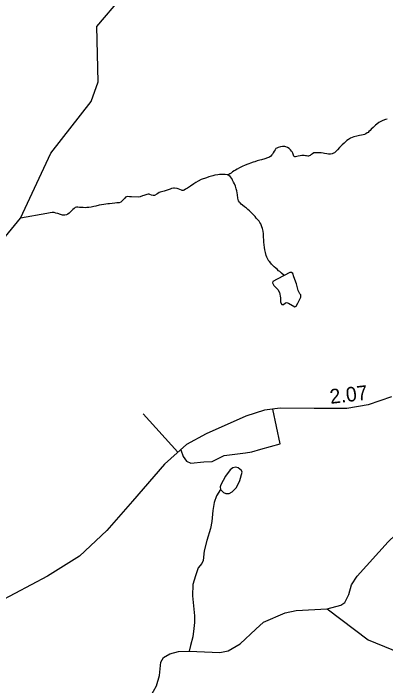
# Model space of a CAD drawing. Extents: x 2056842 to 2160602, y 826753 to 1016856.
# Drawn here: x 2117511 to 2120707, y 858312 to 864081 of the extents above; entities that cross this region are included whole.
import ezdxf

# ---------------------------------------------------------------- set-up
doc = ezdxf.new("R2010")
doc.units = 0
for name, color, linetype in [('Exist Hydrographic Creek Single Shore', 7, 'Continuous'), ('Exist Hydrographic Misc Water Feature', 7, 'Continuous'), ('Exist Road Non-System Type 51', 7, 'Continuous'), ('Exist Road Secondary Mileage Hundredths English Label', 7, 'Continuous'), ('Exist Road Secondary Type 51 Attributed', 7, 'Continuous')]:
    doc.layers.add(name, color=color, linetype=linetype)

msp = doc.modelspace()

# ---------------------------------------------------------------- linework, layer by layer
at = {"layer": 'Exist Hydrographic Creek Single Shore'}
for points in [[(2116978.9, 861602.5), (2117571.4, 862322.8), (2117831.9, 862880.9), (2118179.9, 863326.5), (2118237.9, 863492.7), (2118226.8, 863968.7), (2118442.7, 864224.9)], [(2120721.8, 863174.4), (2120706.1, 863169.9), (2120684.1, 863162.3), (2120666.1, 863153.7), (2120650.5, 863143.9), (2120632.2, 863129.6), (2120622, 863121.8), (2120612.8, 863113.9), (2120600.3, 863103.2), (2120584.5, 863087.4), (2120574.6, 863076.6), (2120565, 863067.2), (2120556.6, 863059.9), (2120549, 863055.4), (2120538.9, 863048.8), (2120525.2, 863042.4), (2120515, 863040.2), (2120501.2, 863036.2), (2120484.8, 863032.6), (2120461.2, 863028.1), (2120435.2, 863022.3), (2120419.2, 863015.8), (2120405.5, 863009.8), (2120389.7, 862999.6), (2120375.7, 862989.2), (2120351.9, 862968.8), (2120333.9, 862952.9), (2120312.4, 862930.5), (2120294.5, 862910.1), (2120286.1, 862900.8), (2120268.5, 862886), (2120259.5, 862880.5), (2120249, 862876.8), (2120235.5, 862874.4), (2120218.4, 862874.1), (2120202.7, 862876.2), (2120182.8, 862879.6), (2120170.5, 862881.8), (2120154.5, 862883.9)], [(2120154.5, 862883.9), (2120134.8, 862884.8), (2120120.4, 862885.4), (2120106.7, 862884.6), (2120092.3, 862883.2), (2120080.2, 862876.8), (2120072.4, 862870.8), (2120066.7, 862866.8), (2120061, 862862.8), (2120052.6, 862858.7), (2120046.6, 862856.4), (2120038.6, 862856.4), (2120028.8, 862858.2), (2120018.9, 862860.2), (2120008.7, 862862.1), (2120000.5, 862862.1), (2119989, 862861.4), (2119972.8, 862859.4), (2119957, 862855.8), (2119944.9, 862851.9), (2119934.7, 862849.7), (2119928.7, 862849.8), (2119923.8, 862853), (2119920.7, 862857.2), (2119917, 862865.4), (2119910.7, 862881.4), (2119904.5, 862892.9), (2119900.4, 862899.6), (2119892.2, 862909), (2119878.1, 862922.8), (2119864.9, 862931.3), (2119850.2, 862936.9), (2119842, 862938.5), (2119822.1, 862939), (2119804.2, 862936.1), (2119783.9, 862929.8), (2119774.5, 862926), (2119766.3, 862920.4), (2119758.3, 862910.6), (2119749.3, 862897.7), (2119742.3, 862884.2), (2119736.4, 862873.3), (2119730, 862866.1), (2119722.2, 862857.2), (2119709.7, 862848.6), (2119694.1, 862841.6), (2119669.3, 862833.1), (2119640.8, 862825.3), (2119627.3, 862820.8), (2119605.5, 862814.9), (2119585.2, 862808.5), (2119571.1, 862804.6), (2119547.5, 862796), (2119531.7, 862790.7), (2119515.3, 862783.8), (2119495.4, 862775.9), (2119481.5, 862769.5), (2119469.4, 862763.2), (2119452.8, 862754.8), (2119433.7, 862745.1), (2119419.6, 862737.1), (2119408.1, 862729.5), (2119393.9, 862720.7), (2119380, 862711), (2119370.4, 862703.9), (2119362.1, 862698.3), (2119353.7, 862695.9)], [(2119353.7, 862695.9), (2119348.2, 862695.9), (2119330.8, 862699), (2119310.3, 862700), (2119292.2, 862699.5), (2119280.5, 862698.5), (2119266.6, 862696.2), (2119242.2, 862691.7), (2119224.8, 862687), (2119190.7, 862678.8), (2119168.6, 862671.2), (2119152.6, 862664.7), (2119140.5, 862660.9), (2119122.4, 862654.7), (2119097, 862642.3), (2119076.7, 862630.3), (2119059.5, 862618.3), (2119031.4, 862597.5), (2119023.2, 862592.2), (2119005.4, 862581.9), (2118989.6, 862571.4), (2118977.9, 862565), (2118968.4, 862561.9), (2118960, 862562), (2118953.9, 862563), (2118941.6, 862569.2), (2118927.4, 862575.1), (2118917.8, 862578.6), (2118895.5, 862582.3), (2118885.2, 862582.7), (2118870, 862578), (2118857.7, 862572.6), (2118841.3, 862566.2), (2118822.9, 862560.1), (2118806, 862555.7), (2118783.7, 862549.3), (2118771.8, 862547.1), (2118764, 862543.4), (2118751.9, 862535.1), (2118742.1, 862528.9), (2118722.2, 862518.9), (2118710.3, 862519.1), (2118695.9, 862522.5), (2118683.8, 862526.8), (2118676.5, 862530.4), (2118667.8, 862530.4), (2118657.8, 862528.3), (2118631.8, 862518), (2118620.1, 862514.1), (2118600, 862508.2), (2118581.9, 862503.6), (2118525.9, 862507.3), (2118507.7, 862507.6), (2118492.1, 862508.7), (2118482.3, 862507.4), (2118474.3, 862503.3), (2118464, 862492.7), (2118454.2, 862482.4), (2118448.2, 862474.4), (2118442.7, 862468.7), (2118433.5, 862461.7), (2118420.5, 862456.6), (2118400.7, 862454), (2118382.8, 862451.8), (2118358.8, 862449.8), (2118336.7, 862447.8), (2118320.7, 862445.8), (2118304.7, 862443.8), (2118287.3, 862441.6), (2118269, 862439.4), (2118248.7, 862435.2), (2118219, 862426.7), (2118200.9, 862423), (2118178.8, 862418.2), (2118158.9, 862416.4), (2118141.3, 862414.2), (2118127.1, 862413.5), (2118108.9, 862414.2), (2118089, 862415.1), (2118077.5, 862416.6), (2118063.1, 862417.5), (2118052.1, 862417.5), (2118041.8, 862414.6), (2118033.4, 862407.3), (2118022.7, 862397.6), (2118011.3, 862386.8), (2118001.6, 862376.9), (2117989.5, 862366.5), (2117977.4, 862357), (2117968, 862351.6), (2117953.9, 862348.4), (2117933.3, 862350.3), (2117914.3, 862355.7), (2117893.4, 862362.8), (2117875.5, 862368), (2117860.3, 862371.5), (2117843.3, 862371.2), (2117827.7, 862369.1), (2117797.4, 862363.1), (2117571.4, 862322.8)]]:
    msp.add_lwpolyline(points, dxfattribs=at)
at = {"layer": 'Exist Hydrographic Misc Water Feature'}
for points in [[(2119835.3, 861830.9), (2119812.4, 861853.1), (2119798.3, 861865), (2119788, 861872.6), (2119776.6, 861884.9), (2119764.3, 861895.3), (2119751.3, 861907), (2119739.6, 861917.7), (2119728.2, 861928.7), (2119712, 861948.6), (2119706, 861956), (2119696, 861972.2), (2119687.6, 861988.4), (2119681.4, 862004.4), (2119675.1, 862028.1), (2119671, 862052.2), (2119667.1, 862071.9), (2119664, 862094.6), (2119662.3, 862118), (2119661.1, 862140.2), (2119660.3, 862158.2), (2119658, 862173.9), (2119657.8, 862190.2), (2119656, 862211.5), (2119649.4, 862234.1), (2119645.1, 862249.2), (2119639, 862266.1), (2119635.3, 862276), (2119628.9, 862286.7), (2119620.9, 862297.6), (2119607, 862313.5), (2119596.7, 862325.2), (2119586.9, 862337.6), (2119574.8, 862349.2), (2119562.5, 862362.8), (2119550.6, 862375.2), (2119538.5, 862387.1), (2119524.3, 862398.6), (2119512, 862409.1), (2119496, 862420.8), (2119479.6, 862434.2), (2119466.5, 862445.2), (2119457.5, 862454.2), (2119452, 862461.6), (2119445.6, 862471.8), (2119439.2, 862495.5), (2119435.1, 862523.7), (2119433.1, 862540.3), (2119430, 862557.3), (2119424.7, 862575.7), (2119418.5, 862597.6), (2119410.3, 862617.6), (2119401.9, 862633.4), (2119393.9, 862649.3), (2119386.1, 862663.4), (2119372.8, 862680.1), (2119353.7, 862695.9)], [(2119835.3, 861830.9), (2119777.5, 861800.7), (2119738.6, 861779.3), (2119737.3, 861768), (2119747.4, 861746.7), (2119781.3, 861711.5), (2119797.6, 861685.1), (2119803.9, 861639.9), (2119806.4, 861602.2), (2119816.4, 861583.3), (2119830.2, 861583.3), (2119846.6, 861598.4), (2119856.6, 861600.9), (2119874.2, 861593.4), (2119929.4, 861563.2), (2119939.5, 861569.5), (2119954.6, 861593.4), (2119978.4, 861644.9), (2119979.7, 861666.3), (2119972.1, 861675.1), (2119957.1, 861702.7), (2119942, 861759.2), (2119920.7, 861820.8), (2119911.9, 861848.4), (2119899.3, 861857.2), (2119885.5, 861857.2), (2119835.3, 861830.9)], [(2120205.7, 858970), (2120322.9, 859000.6), (2120356.4, 859024), (2120392.8, 859093.1), (2120413.7, 859175.9), (2120463.1, 859250.2), (2120728.9, 859546.7), (2120986.7, 859793), (2121019.8, 859839.3), (2121060.9, 859946.7), (2121084.7, 860097), (2121152.5, 860255.3), (2121202.7, 860369.6), (2121265.7, 860615.1), (2121373.8, 860757.3), (2121522.8, 860872.3), (2121913.4, 861039.3), (2122082.9, 861099.6), (2122200.9, 861098.4), (2122526.2, 861098.4), (2122650.5, 861131), (2122864, 861225)], [(2119290.3, 859995.2), (2119314.2, 859968.9), (2119334.2, 859960.1), (2119363.1, 859960.1), (2119390.7, 859973.9), (2119427.2, 860011.6), (2119456, 860070.6), (2119476.1, 860144.7), (2119471.1, 860158.6), (2119442.2, 860181.2), (2119420.9, 860186.2), (2119395.8, 860181.2), (2119373.2, 860163.6), (2119331.7, 860108.3), (2119291.6, 860035.4), (2119286.5, 860016.6), (2119290.3, 859995.2)], [(2119290.3, 859995.2), (2119255.1, 859940), (2119236.3, 859883.4), (2119223.7, 859815.6), (2119215, 859720.1), (2119203.7, 859661), (2119172.3, 859558), (2119149.7, 859468.8), (2119140.9, 859384.6), (2119129.6, 859359.5), (2119096.9, 859321.8), (2119074.3, 859254), (2119051.7, 859178.6), (2119050.5, 859080.6), (2119059.3, 858966.2), (2119066.8, 858909.7), (2119066.8, 858854.4), (2119061.8, 858800.4), (2119051.7, 858728.8), (2119032.9, 858654.6), (2119020.3, 858606.9)], [(2117222.2, 857915.9), (2117523.2, 858055), (2117847.5, 858181), (2117970.6, 858189.8), (2118555.7, 858109.4), (2118585.9, 858121.9), (2118662.5, 858172.2), (2118739.1, 858309.1), (2118766.7, 858397.1), (2118778, 858513.9), (2118799.3, 858551.6), (2118855.8, 858585.5), (2118929.9, 858603.1), (2119020.3, 858606.9), (2119282.8, 858594.3), (2119355.6, 858610.7), (2119458.6, 858671), (2119594.2, 858796.6), (2119657.9, 858856.9), (2119845.3, 858937.3), (2119940.7, 858957.4), (2120205.7, 858970)], [(2120205.7, 858970), (2120557.9, 858703.7), (2121026.9, 858513.9), (2121160, 858486.3), (2121324.5, 858457.4), (2121376, 858458.6), (2121392.3, 858468.7), (2121411.1, 858493.8), (2121442.5, 858566.7), (2121472.7, 858579.3), (2121495.3, 858580.5), (2121570.6, 858554.1), (2121659.7, 858522.7)]]:
    msp.add_lwpolyline(points, dxfattribs=at)
at = {"layer": 'Exist Road Non-System Type 51'}
msp.add_line((2118924.1, 860314), (2118624.1, 860644.2), dxfattribs=at)
msp.add_lwpolyline([(2118948.7, 860336.1), (2118969.9, 860277.3), (2118999, 860237.8), (2119034.3, 860221.2), (2119146.5, 860231.6), (2119217.1, 860233.7), (2119320.9, 860285.6), (2119505.8, 860308.5), (2119558.8, 860317.9), (2119635.6, 860340.7), (2119801.8, 860386.4), (2119740.3, 860684.5)], dxfattribs=at)
at = {"layer": 'Exist Road Secondary Type 51 Attributed'}
msp.add_lwpolyline([(2120759.6, 860791.3), (2120558.2, 860720.9), (2120375.8, 860690.5), (2120093.6, 860689.5), (2119802.9, 860693.3), (2119667.9, 860674.3), (2119506.4, 860624.9), (2119167.2, 860473.7), (2118998.1, 860380.5), (2118810, 860211.3), (2118533.5, 859894.7), (2118314.9, 859643.7), (2118077.4, 859423.1), (2117802.8, 859251), (2117381, 859026.6)], dxfattribs=at)

# ---------------------------------------------------------------- texts
at = {"layer": 'Exist Road Secondary Mileage Hundredths English Label'}
msp.add_text('2.07', height=125, rotation=6.67121, dxfattribs=at).set_placement((2120235.3, 860729.5))

doc.saveas('drawing.dxf')
